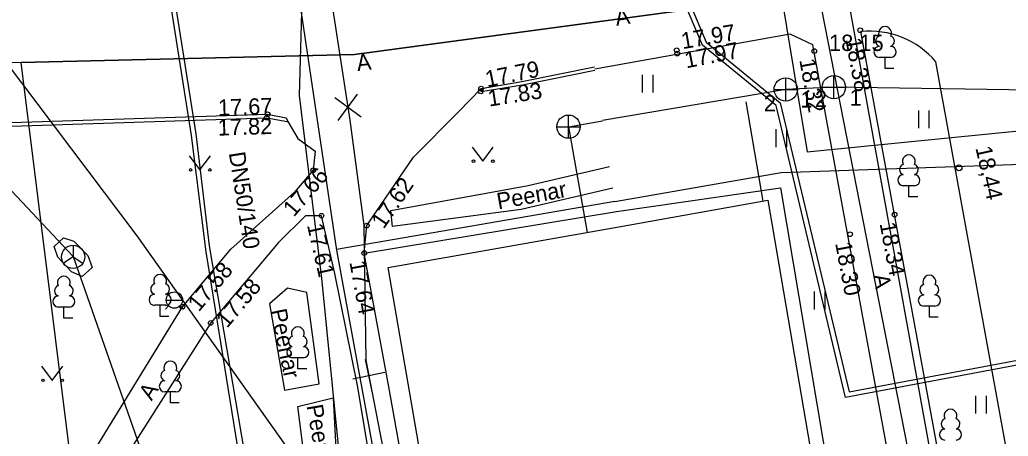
# Model space of a CAD drawing. Extents: x 713497 to 713863, y 6590062 to 6590327.
# Drawn here: x 713604.95 to 713647.37, y 6590142.1 to 6590159.98 of the extents above; entities that cross this region are included whole.
import ezdxf

# ---------------------------------------------------------------- set-up
doc = ezdxf.new("R2010")
doc.units = 0
for name, color, linetype in [('AED', 7, 'Continuous'), ('HALJASTUS', 7, 'Continuous'), ('HOONE', 7, 'Continuous'), ('HOONEDET', 7, 'Continuous'), ('KKAEV', 7, 'Continuous'), ('KORGUS', 7, 'Continuous'), ('KTRASS', 7, 'Continuous'), ('MPKAABEL', 7, 'Continuous'), ('PUU', 7, 'Continuous'), ('SIKAEV', 7, 'Continuous'), ('SITRASS', 7, 'Continuous'), ('TEE', 7, 'Continuous'), ('TKAEV', 7, 'Continuous'), ('TORU NR', 7, 'Continuous'), ('TTRASS', 7, 'Continuous'), ('VKAEV', 7, 'Continuous'), ('VTRASS', 7, 'Continuous'), ('Слой 1', 7, 'Continuous')]:
    doc.layers.add(name, color=color, linetype=linetype)

msp = doc.modelspace()

# ---------------------------------------------------------------- linework, layer by layer
at = {"layer": 'AED'}
msp.add_lwpolyline([(713636.111, 6590156.459), (713636.839, 6590152.192)], dxfattribs=at)
at = {"layer": 'HALJASTUS'}
for p, q in [((713631.668, 6590157.611), (713631.668, 6590156.85)), ((713632.123, 6590157.611), (713632.123, 6590156.85)), ((713643.517, 6590156.084), (713643.517, 6590155.323)), ((713643.972, 6590156.084), (713643.972, 6590155.323)), ((713637.404, 6590155.274), (713637.404, 6590154.513)), ((713637.859, 6590155.274), (713637.859, 6590154.513)), ((713624.363, 6590154.51), (713624.827, 6590153.903)), ((713624.827, 6590153.903), (713625.272, 6590154.51)), ((713612.221, 6590154.136), (713612.685, 6590153.529)), ((713612.685, 6590153.529), (713613.13, 6590154.136)), ((713639.047, 6590148.305), (713639.047, 6590147.544)), ((713639.502, 6590148.305), (713639.502, 6590147.544)), ((713605.884, 6590145.104), (713606.347, 6590144.497)), ((713606.347, 6590144.497), (713606.793, 6590145.104)), ((713645.974, 6590143.84), (713645.974, 6590143.078)), ((713646.429, 6590143.84), (713646.429, 6590143.078))]:
    msp.add_line(p, q, dxfattribs=at)
for points in [[(713620.943, 6590151.106), (713620.871, 6590151.792), (713626.768, 6590152.863), (713630.262, 6590153.67)], [(713630.402, 6590152.751), (713626.466, 6590151.837), (713620.943, 6590151.106)], [(713617.277, 6590148.265), (713616.445, 6590148.453), (713615.662, 6590147.785), (713616.312, 6590144.081), (713617.801, 6590144.348), (713617.277, 6590148.265)], [(713616.888, 6590143.379), (713618.4, 6590143.75), (713618.599, 6590139.924), (713617.323, 6590139.9), (713616.888, 6590143.379)]]:
    msp.add_lwpolyline(points, dxfattribs=at)
for centre in [(713624.426, 6590153.903), (713625.255, 6590153.903), (713612.284, 6590153.529), (713613.112, 6590153.529), (713605.946, 6590144.497), (713606.775, 6590144.497)]:
    msp.add_circle(centre, 0.055, dxfattribs=at)
at = {"layer": 'HOONE'}
for points in [[(713531.39, 6590210.93), (713553.18, 6590202.08), (713559.641, 6590199.405), (713560.352, 6590199.111), (713572.19, 6590194.21), (713578.796, 6590192.061), (713596.274, 6590168.882), (713604.327, 6590158.202), (713609.981, 6590150.703), (713616.91, 6590140.92), (713619.729, 6590126.378), (713620.17, 6590123.82), (713622.85, 6590106.14)], [(713620.755, 6590149.344), (713630.655, 6590151.086), (713637.063, 6590152.231), (713640.875, 6590129.877), (713631.804, 6590128.391), (713624.588, 6590127.182), (713620.755, 6590149.344)]]:
    msp.add_lwpolyline(points, dxfattribs=at)
at = {"layer": 'HOONEDET'}
msp.add_lwpolyline([(713630.555, 6590151.746), (713637.606, 6590152.762), (713641.533, 6590129.374), (713623.856, 6590126.36), (713622.073, 6590136.806), (713621.833, 6590136.805), (713621.356, 6590139.336), (713621.643, 6590139.419), (713620.79, 6590144.22), (713619.738, 6590149.958), (713630.555, 6590151.746)], dxfattribs=at)
at = {"layer": 'KKAEV'}
for p, q in [((713637.825, 6590156.484), (713637.825, 6590157.484)), ((713639.892, 6590156.582), (713639.892, 6590157.582)), ((713637.325, 6590156.984), (713638.325, 6590156.984)), ((713639.392, 6590157.082), (713640.392, 6590157.082)), ((713628.504, 6590154.886), (713628.504, 6590155.886)), ((713628.004, 6590155.386), (713629.004, 6590155.386))]:
    msp.add_line(p, q, dxfattribs=at)
for centre in [(713637.825, 6590156.984), (713639.892, 6590157.082), (713628.504, 6590155.386)]:
    msp.add_circle(centre, 0.5, dxfattribs=at)
at = {"layer": 'KORGUS'}
for centre, radius in [((713641.022, 6590159.523), 0.1), ((713633.144, 6590158.668), 0.1), ((713633.166, 6590158.526), 0.1), ((713639.048, 6590158.631), 0.1), ((713624.732, 6590156.9), 0.1), ((713624.752, 6590157.024), 0.1), ((713615.585, 6590155.92), 0.1), ((713615.553, 6590155.767), 0.1), ((713617.544, 6590153.514), 0.1), ((713645.26, 6590153.62), 0.125), ((713617.9, 6590151.566), 0.1), ((713642.494, 6590151.612), 0.1), ((713619.844, 6590151.142), 0.1), ((713640.585, 6590150.766), 0.1), ((713619.738, 6590149.958), 0.1), ((713611.932, 6590147.658), 0.1), ((713613.144, 6590146.96), 0.1)]:
    msp.add_circle(centre, radius, dxfattribs=at)
at = {"layer": 'KTRASS'}
for p, q in [((713637.825, 6590156.984), (713629.96, 6590155.655)), ((713639.892, 6590157.082), (713637.825, 6590156.984)), ((713656.03, 6590156.825), (713639.892, 6590157.082))]:
    msp.add_line(p, q, dxfattribs=at)
for points in [[(713628.504, 6590155.386), (713629.963, 6590155.638)], [(713628.504, 6590155.386), (713629.302, 6590150.848)]]:
    msp.add_lwpolyline(points, dxfattribs=at)
at = {"layer": 'MPKAABEL'}
for points in [[(713614.229, 6590177.468), (713614.715, 6590176.812), (713616.87, 6590161.36), (713618.55, 6590150.08)], [(713623.164, 6590135.391), (713619.07, 6590137.22), (713617.908, 6590148.88), (713616.96, 6590156.73), (713617.053, 6590160.295), (713617.928, 6590165.834), (713616.95, 6590174.44)], [(713628.364, 6590166.869), (713632.08, 6590167.48), (713633.015, 6590162.313), (713634.41, 6590159.02), (713637.59, 6590156.404), (713640.542, 6590143.998), (713655.527, 6590146.824), (713666.053, 6590148.923), (713666.104, 6590148.937), (713666.053, 6590148.923), (713676.52, 6590152.11), (713677.82, 6590153.38), (713679.31, 6590155.11), (713679.81, 6590159.44), (713679.75, 6590161.04), (713679.53, 6590162.08), (713679.1, 6590163.05), (713677.79, 6590165.07), (713675.3, 6590167.39), (713673.09, 6590169.87), (713671.63, 6590170.7), (713670.72, 6590170.92), (713670.037, 6590170.92)], [(713712.95, 6590130.05), (713709.16, 6590129.42), (713701.69, 6590129.47), (713690.5, 6590129.51), (713688.19, 6590129.12), (713683.66, 6590141.1), (713679.81, 6590148.4), (713679.37, 6590149.39), (713679.04, 6590150.26), (713678.83, 6590150.79), (713678.48, 6590151.44), (713677.98, 6590152.02), (713677.43, 6590152.31), (713676.95, 6590152.28), (713676.524, 6590152.014), (713670.183, 6590149.934), (713666.077, 6590148.723), (713655.565, 6590146.628), (713640.392, 6590143.766), (713637.411, 6590156.292), (713634.246, 6590158.892), (713632.822, 6590162.256), (713631.92, 6590167.25), (713628.288, 6590166.652)], [(713674.28, 6590157.49), (713668.35, 6590156.18), (713665.344, 6590155.743), (713665.26, 6590155.731), (713652.94, 6590153.94), (713637.63, 6590153.4), (713630.492, 6590152.158)], [(713630.49, 6590152.173), (713618.54, 6590150.12)], [(713618.55, 6590150.08), (713621.03, 6590136.49), (713622.8, 6590126.219), (713623.046, 6590124.788), (713623.53, 6590121.98), (713626.07, 6590107.43), (713629.2, 6590089.44), (713630.873, 6590079.95)]]:
    msp.add_lwpolyline(points, dxfattribs=at)
at = {"layer": 'PUU'}
for p, q in [((713642.326, 6590158.359), (713641.846, 6590158.359)), ((713642.086, 6590157.884), (713642.086, 6590158.359)), ((713642.466, 6590157.884), (713642.086, 6590157.884)), ((713643.349, 6590152.852), (713642.869, 6590152.852)), ((713643.109, 6590152.377), (713643.109, 6590152.852)), ((713643.489, 6590152.377), (713643.109, 6590152.377)), ((713607.083, 6590147.644), (713606.603, 6590147.644)), ((713606.843, 6590147.169), (713606.843, 6590147.644)), ((713611.213, 6590147.718), (713610.733, 6590147.718)), ((713610.973, 6590147.243), (713610.973, 6590147.718)), ((713644.229, 6590147.688), (713643.749, 6590147.688)), ((713643.989, 6590147.213), (713643.989, 6590147.688)), ((713607.223, 6590147.169), (713606.843, 6590147.169)), ((713611.353, 6590147.243), (713610.973, 6590147.243)), ((713644.369, 6590147.213), (713643.989, 6590147.213)), ((713617.124, 6590145.467), (713616.644, 6590145.467)), ((713616.884, 6590144.992), (713616.884, 6590145.467)), ((713617.264, 6590144.992), (713616.884, 6590144.992)), ((713611.653, 6590144.003), (713611.173, 6590144.003)), ((713611.413, 6590143.528), (713611.413, 6590144.003)), ((713611.793, 6590143.528), (713611.413, 6590143.528))]:
    msp.add_line(p, q, dxfattribs=at)
for centre, radius, start, end in [((713642.086, 6590159.404), 0.277, 332.5799, 207.4201), ((713641.916, 6590159.056), 0.233, 109.0217, 253.1415), ((713642.256, 6590159.056), 0.233, 286.8508, 70.9859), ((713641.849, 6590158.596), 0.238, 90.0016, 269.3953), ((713642.323, 6590158.596), 0.238, 270.6047, 89.9984), ((713643.109, 6590153.897), 0.277, 332.5799, 207.4201), ((713642.939, 6590153.549), 0.233, 109.0217, 253.1415), ((713643.279, 6590153.549), 0.233, 286.8508, 70.9859), ((713642.871, 6590153.089), 0.238, 90.0016, 269.3953), ((713643.346, 6590153.089), 0.238, 270.6047, 89.9984), ((713606.843, 6590148.689), 0.277, 332.5799, 207.4201), ((713610.973, 6590148.763), 0.277, 332.5799, 207.4201), ((713643.989, 6590148.733), 0.277, 332.5799, 207.4201), ((713606.673, 6590148.342), 0.233, 109.0217, 253.1415), ((713607.013, 6590148.342), 0.233, 286.8508, 70.9859), ((713610.803, 6590148.416), 0.233, 109.0217, 253.1415), ((713611.143, 6590148.416), 0.233, 286.8508, 70.9859), ((713643.819, 6590148.386), 0.233, 109.0217, 253.1415), ((713644.159, 6590148.386), 0.233, 286.8508, 70.9859), ((713606.606, 6590147.881), 0.238, 90.0016, 269.3953), ((713607.08, 6590147.881), 0.238, 270.6047, 89.9984), ((713610.736, 6590147.955), 0.238, 90.0016, 269.3953), ((713611.21, 6590147.955), 0.238, 270.6047, 89.9984), ((713643.752, 6590147.926), 0.238, 90.0016, 269.3953), ((713644.227, 6590147.926), 0.238, 270.6047, 89.9984), ((713616.884, 6590146.512), 0.277, 332.5799, 207.4201), ((713616.714, 6590146.165), 0.233, 109.0217, 253.1415), ((713617.054, 6590146.165), 0.233, 286.8508, 70.9859), ((713616.647, 6590145.704), 0.238, 90.0016, 269.3953), ((713617.121, 6590145.704), 0.238, 270.6047, 89.9984), ((713611.413, 6590145.048), 0.277, 332.5799, 207.4201), ((713611.243, 6590144.701), 0.233, 109.0217, 253.1415), ((713611.583, 6590144.701), 0.233, 286.8508, 70.9859), ((713611.176, 6590144.24), 0.238, 90.0016, 269.3953), ((713611.65, 6590144.24), 0.238, 270.6047, 89.9984), ((713644.726, 6590142.63), 0.233, 109.0217, 253.1415), ((713644.897, 6590142.978), 0.277, 332.5799, 207.4201), ((713645.067, 6590142.63), 0.233, 286.8508, 70.9859), ((713644.659, 6590142.17), 0.238, 90.0016, 269.3953), ((713645.134, 6590142.17), 0.238, 270.6047, 89.9984)]:
    msp.add_arc(centre, radius, start, end, dxfattribs=at)
at = {"layer": 'SIKAEV'}
for p, q in [((713607.241, 6590150.296), (713607.241, 6590149.796)), ((713607.241, 6590149.796), (713606.826, 6590149.521)), ((713607.241, 6590149.796), (713607.656, 6590149.521))]:
    msp.add_line(p, q, dxfattribs=at)
msp.add_circle((713607.241, 6590149.796), 0.5, dxfattribs=at)
at = {"layer": 'SITRASS'}
for p, q in [((713618.469, 6590156.637), (713619.597, 6590155.807)), ((713618.618, 6590155.658), (713619.448, 6590156.786)), ((713620.08, 6590144.019), (713619.794, 6590145.39)), ((713619.252, 6590144.562), (713620.622, 6590144.847))]:
    msp.add_line(p, q, dxfattribs=at)
for points in [[(713631.121, 6590185.897), (713633.455, 6590186.339), (713638.75, 6590154.309), (713660.08, 6590156.42), (713665.095, 6590157.143)], [(713583.469, 6590179.204), (713587.125, 6590174.133), (713591.164, 6590169.577), (713596.109, 6590163.101), (713600.06, 6590157.809), (713602.836, 6590154.49), (713607.246, 6590149.813), (713612.534, 6590134.682), (713614.495, 6590126.756), (713617.08, 6590112.11), (713617.08, 6590112.12), (713617.47, 6590112.1), (713633.79, 6590115.93), (713633.915, 6590115.958)], [(713619.005, 6590170.338), (713616.91, 6590169.95), (713619.12, 6590155.66), (713619.72, 6590151.16), (713619.81, 6590145.36), (713621.97, 6590134.21), (713623.094, 6590127.673)]]:
    msp.add_lwpolyline(points, dxfattribs=at)
msp.add_lwpolyline([(713607.635, 6590148.959), (713607.166, 6590149.158), (713606.59, 6590149.78), (713606.433, 6590150.236), (713606.821, 6590150.619), (713607.278, 6590150.469), (713607.868, 6590149.857), (713608.053, 6590149.339)], close=True, dxfattribs=at)
at = {"layer": 'TEE'}
for points in [[(713647.309, 6590125.395), (713641.049, 6590159.467)], [(713638.989, 6590158.893), (713638.009, 6590159.352), (713629.627, 6590157.85)], [(713645.25, 6590124.822), (713638.989, 6590158.893)], [(713649.897, 6590127.23), (713644.271, 6590158.171)], [(713619.738, 6590149.958), (713619.738, 6590149.958), (713619.844, 6590151.142), (713621.85, 6590154.074), (713623.784, 6590156.028), (713624.752, 6590157.024), (713626.503, 6590157.319), (713629.611, 6590157.95)], [(713624.732, 6590156.9), (713626.523, 6590157.18), (713629.633, 6590157.81)], [(713582.979, 6590144.025), (713585.225, 6590149.685), (713586.881, 6590153.949), (713586.941, 6590154.043), (713587.496, 6590154.576), (713588.27, 6590155.034), (713601.932, 6590155.483), (713615.585, 6590155.92), (713616.388, 6590155.765), (713616.462, 6590155.606), (713616.882, 6590154.875)], [(713587.039, 6590153.93), (713587.568, 6590154.459), (713588.26, 6590154.862), (713601.944, 6590155.323), (713615.553, 6590155.767), (713616.429, 6590155.608), (713616.462, 6590155.606)], [(713616.882, 6590154.875), (713617.628, 6590154.342), (713617.544, 6590153.514)], [(713617.544, 6590153.514), (713616.741, 6590152.582), (713614.005, 6590150.134)], [(713566.967, 6590153.208), (713562.59, 6590143.13), (713560.84, 6590139.13), (713560.56, 6590138.35), (713557.65, 6590125.67), (713556.37, 6590120.11), (713556.68, 6590119.84), (713558.67, 6590119.06), (713576.02, 6590111.53), (713584, 6590107.76), (713588.86, 6590105.77), (713590.57, 6590105.1), (713590.77, 6590105.14), (713591.5, 6590107.05), (713594.07, 6590113.35), (713596.09, 6590118.23), (713597.57, 6590121.81), (713599.83, 6590126.13), (713602.51, 6590131.08), (713606.52, 6590138.814), (713611.932, 6590147.658), (713614.005, 6590150.134)], [(713620.509, 6590137.915), (713619.454, 6590144.207), (713618.467, 6590149.082), (713617.9, 6590151.566), (713617.22, 6590151.56), (713616.056, 6590150.411), (713613.144, 6590146.96), (713607.413, 6590137.936)]]:
    msp.add_lwpolyline(points, dxfattribs=at)
msp.add_arc((713641.429, 6590155.759), 3.727, 40.3152, 95.8636, dxfattribs=at)
at = {"layer": 'TTRASS'}
for points in [[(713567.466, 6590198.63), (713578.401, 6590193.782), (713589.512, 6590189.073), (713600.569, 6590184.368), (713601.451, 6590183.992), (713601.524, 6590183.896), (713601.155, 6590183.08), (713600.626, 6590181.777), (713600.676, 6590181.533), (713602.872, 6590179.376), (713604.978, 6590177.28), (713605.925, 6590176.311), (713608.173, 6590174), (713608.441, 6590173.865), (713609.351, 6590174.136), (713609.498, 6590174.017), (713612.504, 6590155.073), (713613.075, 6590150.266), (713615.084, 6590138.478)], [(713567.885, 6590198.124), (713578.819, 6590193.334), (713589.871, 6590188.505), (713601.021, 6590183.871), (713601.066, 6590183.741), (713600.225, 6590181.685), (713600.269, 6590181.473), (713605.066, 6590176.79), (713605.92, 6590175.914), (713608.121, 6590173.566), (713608.385, 6590173.433), (713609.208, 6590173.681), (713609.37, 6590173.599), (713612.302, 6590155.005), (713612.943, 6590150.015), (713614.851, 6590138.172)]]:
    msp.add_lwpolyline(points, dxfattribs=at)
at = {"layer": 'VKAEV'}
for p, q in [((713611.238, 6590147.944), (713611.938, 6590147.944)), ((713611.341, 6590147.697), (713611.201, 6590147.557)), ((713611.835, 6590147.697), (713611.975, 6590147.557))]:
    msp.add_line(p, q, dxfattribs=at)
msp.add_circle((713611.588, 6590147.944), 0.35, dxfattribs=at)
at = {"layer": 'VTRASS'}
msp.add_lwpolyline([(713656.584, 6590071.475), (713656.374, 6590072.423), (713654.566, 6590083.572), (713651.757, 6590099.218), (713649.481, 6590111.002), (713648.142, 6590117.611), (713647.31, 6590122.509), (713646.414, 6590125.725), (713646.252, 6590126.242), (713646.237, 6590126.353), (713646.208, 6590126.464), (713646.178, 6590126.898), (713644.112, 6590140.998), (713641.664, 6590154.51), (713639.62, 6590165.841), (713639.136, 6590167.772), (713636.504, 6590183.972), (713635.775, 6590189.972), (713635.261, 6590195.956), (713632.54, 6590225.141)], dxfattribs=at)
at = {"layer": 'Слой 1'}
for points in [[(713639.21, 6590161.17), (713619.31, 6590158.48), (713605.01, 6590158.14), (713587.01, 6590157.64), (713579.15, 6590161.09), (713575.14, 6590170.32), (713594.16, 6590210.61), (713559.07, 6590225.5), (713569.4, 6590249.89), (713586.61, 6590242.91), (713588.04, 6590239.97), (713627.31, 6590223.7), (713629.09, 6590219.58), (713632.13, 6590197.39)], [(713605.01, 6590158.14), (713619.31, 6590158.48), (713639.21, 6590161.17), (713646.6, 6590123.47), (713610.16, 6590116.83)]]:
    msp.add_lwpolyline(points, close=True, dxfattribs=at)

# ---------------------------------------------------------------- texts
at = {"layer": 'HALJASTUS'}
for rotation, p in [(10.2937, (713625.491, 6590151.834)), (281.6266, (713615.702, 6590147.499)), (279.6519, (713617.258, 6590143.408))]:
    msp.add_text('Peenar', height=0.7, rotation=rotation, dxfattribs=at).set_placement(p)
at = {"layer": 'KORGUS'}
for s, rotation, p in [(' 17.97', 9.717, (713633.144, 6590158.668)), (' 17.97', 11.1761, (713633.302, 6590157.839)), (' 18.38', 280.5405, (713640.334, 6590159.395)), (' 17.79', 11.4824, (713624.752, 6590157.024)), (' 18.32', 280.1842, (713638.359, 6590158.507)), (' 17.83', 8.8855, (713624.84, 6590156.208)), (' 17.67', 1.8333, (713613.206, 6590155.844)), (' 17.82', 1.8333, (713613.197, 6590154.991)), ('18,44', 282.3666, (713645.964, 6590154.477)), (' 17.66', 49.2522, (713616.544, 6590151.281)), (' 17.62', 55.6211, (713620.422, 6590150.747)), (' 17.61', 282.8581, (713617.218, 6590151.41)), (' 18.34', 280.5405, (713641.806, 6590151.484)), (' 18.30', 280.5405, (713639.897, 6590150.638)), (' 17.58', 50.0627, (713612.469, 6590147.209)), (' 17.64', 280.3892, (713619.049, 6590149.832)), (' 17.58', 49.8419, (713613.679, 6590146.509))]:
    msp.add_text(s, height=0.7, rotation=rotation, dxfattribs=at).set_placement(p)
msp.add_text('18,15', height=0.7, dxfattribs=at).set_placement((713639.683, 6590158.635))
at = {"layer": 'TEE'}
for rotation, p in [(9.1345, (713630.559, 6590159.714)), (6.9563, (713619.447, 6590157.768)), (280.4969, (713641.572, 6590148.999)), (58.5359, (713610.609, 6590143.591))]:
    msp.add_text('A', height=0.7, rotation=rotation, dxfattribs=at).set_placement(p)
at = {"layer": 'TKAEV'}
msp.add_text('DN50/140', height=0.7, rotation=278.9146, dxfattribs=at).set_placement((713613.921, 6590154.256))
at = {"layer": 'TORU NR'}
for s, p in [('1', (713638.455, 6590156.206)), ('2', (713639.077, 6590156.229)), ('1', (713640.563, 6590156.289)), ('2', (713636.885, 6590156.039))]:
    msp.add_text(s, height=0.7, dxfattribs=at).set_placement(p)

doc.saveas('drawing.dxf')
